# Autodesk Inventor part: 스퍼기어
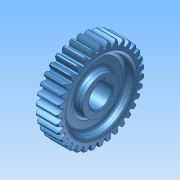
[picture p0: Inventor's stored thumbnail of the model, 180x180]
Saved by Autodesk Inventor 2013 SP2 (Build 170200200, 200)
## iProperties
Created: 2025-08
Part Number: 스퍼기어
Material: Generic
Document SubType Name: Modeling
Designer: i
Density: 1 g/cm^3
Author: i
변환 표준: STEP AP214IS
전처리기: Build: 200, Release: 2013 SP2 Update 6 - Date: Thu 07/17/2014
전송 단위: 밀리미터
불확실성: 0.01
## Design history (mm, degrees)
node "스퍼기어1"
node "솔리드1"
node "기준1"
